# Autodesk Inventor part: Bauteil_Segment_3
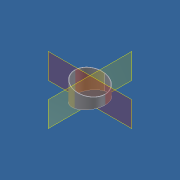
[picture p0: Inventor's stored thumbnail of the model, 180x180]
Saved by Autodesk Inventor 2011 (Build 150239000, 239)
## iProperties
Created: 2009-03
Part Number: Bauteil_Segment_3
Material: S235JR
Document SubType Name: Blech
Designer: Guido Walteich
Density: 7.86 g/cm^3
Flat Pattern Width: 49.112 cm
Flat Pattern Length: 9.54779 cm
Flat Pattern Area: 468.911 cm^2
Description: Blech
Mass: 738.822 g
Surface Area: 660.584 cm^2
Volume: 93.9977 cm^3
Sheet Metal Rule: Standard_mm
Stärke: 3 mm
d0: 160 mm
d6: 95 mm
Gestr_Neutral: 491 mm
Maße: = Ø<d0> x L=<d6> , aus Blech <Stärke> x <d6> x <Gestr_neutral>
Author: Guido Walteich
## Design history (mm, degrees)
node "Skizze1"
node "Konturlasche1"
  sketch "Skizze2"
    geometry: L1 (-98, 0)-(98, 0) reference; L2 (0, -98.1)-(0, 98.6) reference; A1 r 80 centre (0, 0) between (-0.5, 79.998) and (0.5, 79.998); A2 r 0.5 centre (0, 80) between (0.5, 79.998) and (-0.5, 79.998)
    constraints: 5 point on circle, 2 centre point, 2 point on line, 1 midpoint
    dimensions: "d0" = 160 diameter of A1 (= Rohr_D); "d1" = 1 diameter of A2
workplane "Arbeitsebene1"
workplane "Arbeitsebene2"
sketch "Skizze6"
  geometry: L1 (80, 0)-(80, 95.478) reference; L2 (-80, 0)-(-80, 95.478) reference; L3 (-80, 95.478)-(80, 95.478) reference; L4 (80, 0)-(-80, 0) reference; L5 (-80, 31.826)-(80, 0); L6 (80, 95.478)-(-80, 63.652); 4 further points
  constraints: 4 end point, 2 point on line
  dimensions: "d21" = 11.25 deg angle of L5 L4 (= WINKEL); "d24" = 11.25 deg angle of L3 L6 (= WINKEL)
extrude "Extrusion2" cut sketch "Skizze6" stored distance "d25" = 320 (= 2 x Rohr_D); taper "d26" = 0 deg
node "Volumenkörper1"
feature "Grobblech1" dims "d2" = 3 (= BreiteBiegungsfreistellung), "d3" = 1.5 (= TiefeBiegungsfreistellung), "d4" = 6 (= MinimalRest), "d5" = 3 (= Biegeradius), "d6" = 95.47792 (= Länge_3), "d7" = 3 (= Biegeradius), "d8" = 3 (= Wandstärke), "d9" = 12 (= GrößeEckenfreistellung), "d10" = 3 (= Stärke), "d11" = 3 (= JacobiRadiusGröße), "Stärke" = 3 (= Wandstärke), "AbstandVerbindung" = 0.01
feature "Biegung1" dims "d2" = 3 (= BreiteBiegungsfreistellung), "d3" = 1.5 (= TiefeBiegungsfreistellung), "d4" = 6 (= MinimalRest), "d5" = 3 (= Biegeradius), "d7" = 3 (= Biegeradius), "d8" = 3 (= Wandstärke), "Stärke" = 3 (= Wandstärke), "AbstandVerbindung" = 0.01
feature "Ecke1" dims "d8" = 3 (= Wandstärke), "d9" = 12 (= GrößeEckenfreistellung), "d10" = 3 (= Stärke), "d11" = 3 (= JacobiRadiusGröße)
feature "Definition1"
other parameters: "KFaktor" = 4.4, "Biegeradius" = 3 (= Stärke), "BreiteBiegungsfreistellung" = 3 (= Stärke), "TiefeBiegungsfreistellung" = 1.5 (= 0.5 x Stärke), "GrößeEckenfreistellung" = 12 (= 4 x Stärke), "MinimalRest" = 6 (= 2 x Stärke), "Übergangsradius" = 3 (= Biegeradius), "JacobiRadiusGröße" = 3 (= Biegeradius), "Rohr_D" = 160 [user parameter; used in 3 equation terms], "WINKEL_2" = 1.9635 [user parameter], "WINKEL_3" = 1.9635 [user parameter], "Länge_3" = 95.47792 [user parameter; used in 1 equation term], "Wandstärke" = 3 [user parameter; used in 3 equation terms], "d12" = 0, "d13" = 0, "Gestr_Neutral" = 490.87375 (computed from Rohr_D, Wandstärke) [user parameter], "WINKEL" = 11.25 deg [user parameter; used in 2 equation terms], "Länge_1" = 47.73896 [user parameter], "Länge_2" = 95.47792 [user parameter], "Länge_4" = 95.47792 [user parameter], "Länge_5" = 47.73896 [user parameter], "GES_WINKEL" = 90 deg [user parameter], "ANZ_TEILE" = 39.78874 [user parameter], "Abstandsgröße" = 3 (= Stärke), "Gestr_Neutral" = 490.87375, "Länge_3" = 95.47792, "WINKEL_2" = 1.9635, "WINKEL_3" = 1.9635, "Wandstärke" = 3, "Biegeradius" = 3, "BreiteBiegungsfreistellung" = 3, "GrößeEckenfreistellung" = 12, "JacobiRadiusGröße" = 3, "MinimalRest" = 6, "Stärke" = 3, "TiefeBiegungsfreistellung" = 1.5, "Übergangsradius" = 3, "Länge_1" = 47.73896, "Länge_2" = 95.47792, "Länge_4" = 95.47792, "Länge_5" = 47.73896, "WINKEL" = 1.9635, "ANZ_TEILE" = 39.78874, "GES_WINKEL" = 90 deg, "Abstandsgröße" = 3
